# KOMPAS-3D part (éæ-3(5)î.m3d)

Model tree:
1. Объединить компоненты:1
2. Эскиз:5
3. Операция выдавливания:3
     Расстояние 1 = 8
4. Скругление:3
     Радиус = 10

Referenced files in D:\Работа\Мещеряков\Сигнализатор ВС\Черновики\: ВС-3(5)М (.057, .058, .059, .068).a3d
